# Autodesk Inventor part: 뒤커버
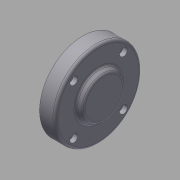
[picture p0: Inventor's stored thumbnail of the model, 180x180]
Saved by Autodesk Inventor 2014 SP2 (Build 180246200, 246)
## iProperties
Company: 한국ATC센터
Created: 2015-12
Part Number: 뒤커버
Document SubType Name: Modeling
Designer: mdu
Density: 2.71 g/cm^3
Mass: 105.756 g
Surface Area: 115.002 cm^2
Volume: 39.0244 cm^3
Material: 알루미늄 6061
Appearance: 알루미늄 - 평지
Author: mdu
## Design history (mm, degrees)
sketch "스케치1"
  geometry: L1 (-10.5, 0)-(10.5, 0); L2 (10.5, 0)-(10.5, 22.5); L3 (10.5, 22.5)-(5.5, 22.5); L4 (5.5, 22.5)-(5.5, 32.5); L5 (5.5, 32.5)-(-6.5, 32.5); L6 (-6.5, 32.5)-(-6.5, 17.5); L7 (-6.5, 17.5)-(-10.5, 15.191); L8 (-10.5, 15.191)-(-10.5, 0); 2 further points
  constraints: 16 end point, 3 parallel, 3 perpendicular, 1 coincident, 1 horizontal, 1 midpoint
  dimensions: "d0" = 21 distance of L1.start L1.end; "d1" = 65 diameter of L5 L1; "d2" = 45 diameter of L3 L1; "d3" = 35 diameter of L6.end L1; "d4" = 120 deg angle of L7 L6; "d5" = 12 distance of L4.end L5.end; "d6" = 5 distance of L2.end L3.end
revolve "회전1" sketch "스케치1" stored, may be unused: angle "d7" = 90 deg
sketch "스케치2"
  geometry: L1 (0, 0)-(32.5, 0); L2 (0, 0)-(18.738, 18.738); 1 further point
  constraints: 4 end point, 1 horizontal, 1 horizontal alignment, 1 other
  dimensions: "d8" = 45 deg angle of L1 L2; "d9" = 26.5 distance of L1.start L2.end
hole "구멍1" sketch "스케치2" at (18.738, 18.738) diameter "d10" = 3.4; stored, may be unused: countersink angle "d14" = 90 deg, drill point angle "d16" = 118 deg; dims "d11" = 6, "d12" = 6, "d13" = 3.3, "d15" = 8
fillet "모깎기1" dims "d20" = 2
hole "구멍2" diameter "d23" = 15; stored, may be unused: countersink angle "d27" = 90 deg, drill point angle "d29" = 0 deg; dims "d21" = 10, "d22" = 10, "d24" = 6, "d25" = 35, "d26" = 11, "d28" = 14
chamfer "모따기1" distance "d39" = 1; stored, may be unused: second distance "d40" = 2, angle "d41" = 45 deg
fillet "모깎기2" dims "d42" = 0.3
chamfer "모따기3" distance "d57" = 1; stored, may be unused: second distance "d58" = 2, angle "d59" = 45 deg
fillet "모깎기4" dims "d60" = 1
node "솔리드1"
pattern_circular "원형 패턴1" dims angle "d18" = 360 deg
